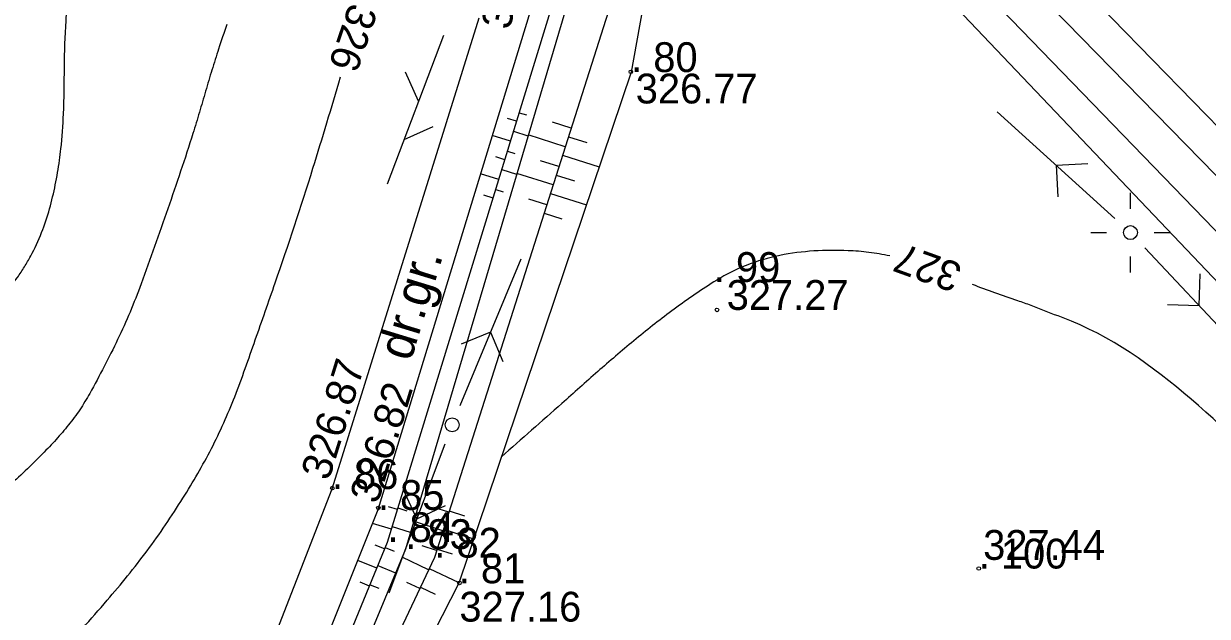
# Model space of a CAD drawing. Extents: x 4632591 to 4653165, y 5351032 to 5369868.
# Drawn here: x 4644706.6 to 4644766.2, y 5358525 to 5358554.8 of the extents above; entities that cross this region are included whole.
import ezdxf

# ---------------------------------------------------------------- set-up
doc = ezdxf.new("R2010")
doc.units = 0
for name, color, linetype in [('EUZPU_424', 7, 'Continuous'), ('SDRPK_420', 7, 'Continuous'), ('UEEPA_510', 7, 'Continuous'), ('UEETA_515', 7, 'Continuous'), ('UEETA_516', 7, 'Continuous'), ('UTTTA_521', 7, 'Continuous'), ('Warstwa 62', 7, 'Continuous'), ('WUKPS_403', 7, 'Continuous'), ('WUKPS_820', 7, 'Continuous'), ('WUKPS_823', 7, 'Continuous'), ('WUKPS_824', 7, 'Continuous'), ('WWRPH_811', 7, 'Continuous')]:
    doc.layers.add(name, color=color, linetype=linetype)

msp = doc.modelspace()

# ---------------------------------------------------------------- linework, layer by layer
at = {"layer": 'EUZPU_424'}
for points in [[(4644736.52, 5358573.425), (4644734.734, 5358569.58), (4644733.014, 5358558.487), (4644724.43, 5358530.37), (4644718.67, 5358515.99), (4644711.55, 5358501.11), (4644708.07, 5358496.17), (4644703.46, 5358490.97), (4644685.13, 5358478.64), (4644676.84, 5358472.22), (4644671.23, 5358466.74), (4644658.94, 5358454.03), (4644646.98, 5358446.31), (4644643, 5358444.41)], [(4644729.51, 5358555.12), (4644722.11, 5358531.42), (4644716.49, 5358516.97), (4644709.43, 5358502.48), (4644706.31, 5358497.61), (4644701.62, 5358493.26), (4644695.208, 5358490.354), (4644683.44, 5358482.53), (4644675.12, 5358474.36), (4644669.43, 5358468.46), (4644657.26, 5358456.17), (4644645.62, 5358448.34)]]:
    msp.add_lwpolyline(points, dxfattribs=at)
at = {"layer": 'SDRPK_420'}
msp.add_lwpolyline([(4644712.764, 5358603.261), (4644713.95, 5358602.19), (4644735.11, 5358581.89), (4644746.11, 5358570.7), (4644757.33, 5358559.27), (4644771.55, 5358544.69), (4644780.39, 5358535.5), (4644785.103, 5358530.718)], dxfattribs=at)
at = {"layer": 'UEEPA_510'}
for centre in [(4644762.316, 5358544.323), (4644728.165, 5358534.653)]:
    msp.add_circle(centre, 0.35, dxfattribs=at)
at = {"layer": 'UEETA_515'}
for p, q in [((4644762.316, 5358545.523), (4644762.316, 5358546.323)), ((4644760.316, 5358544.323), (4644761.116, 5358544.323)), ((4644763.516, 5358544.323), (4644764.316, 5358544.323)), ((4644762.316, 5358542.323), (4644762.316, 5358543.123))]:
    msp.add_line(p, q, dxfattribs=at)
at = {"layer": 'UEETA_516'}
for p, q in [((4644761.539, 5358545.029), (4644755.614, 5358550.404)), ((4644758.576, 5358547.716), (4644760.174, 5358547.794)), ((4644758.576, 5358547.716), (4644758.654, 5358546.119)), ((4644728.567, 5358535.623), (4644731.635, 5358543.011)), ((4644763.036, 5358543.559), (4644768.518, 5358537.732)), ((4644765.777, 5358540.645), (4644765.826, 5358542.244)), ((4644765.777, 5358540.645), (4644764.178, 5358540.694)), ((4644730.101, 5358539.317), (4644728.623, 5358538.706)), ((4644730.101, 5358539.317), (4644730.712, 5358537.839)), ((4644727.794, 5358533.67), (4644724.97, 5358526.186)), ((4644726.382, 5358529.928), (4644725.723, 5358531.386)), ((4644726.382, 5358529.928), (4644727.839, 5358530.587))]:
    msp.add_line(p, q, dxfattribs=at)
at = {"layer": 'UTTTA_521'}
for p, q in [((4644727.725, 5358554.238), (4644724.899, 5358546.754)), ((4644726.478, 5358550.935), (4644725.819, 5358552.392)), ((4644725.747, 5358548.999), (4644727.204, 5358549.658))]:
    msp.add_line(p, q, dxfattribs=at)
at = {"layer": 'WUKPS_403'}
for centre in [(4644737.163, 5358552.412), (4644741.498, 5358540.434), (4644722.135, 5358531.466), (4644724.452, 5358530.466), (4644754.68, 5358527.42), (4644754.68, 5358527.42), (4644728.532, 5358526.697)]:
    msp.add_circle(centre, 0.09, dxfattribs=at)
at = {"layer": 'WUKPS_820'}
for p, q in [((4644731.544, 5358550.352), (4644731.902, 5358550.242)), ((4644731.412, 5358549.923), (4644730.95, 5358550.065)), ((4644734.158, 5358549.572), (4644733.216, 5358549.873)), ((4644731.104, 5358548.921), (4644730.182, 5358549.205)), ((4644731.258, 5358549.422), (4644731.983, 5358549.199)), ((4644733.863, 5358548.646), (4644731.996, 5358549.241)), ((4644734.022, 5358549.145), (4644734.952, 5358548.848)), ((4644730.951, 5358548.421), (4644731.318, 5358548.308)), ((4644730.819, 5358547.991), (4644730.358, 5358548.133)), ((4644733.545, 5358547.647), (4644732.621, 5358547.942)), ((4644733.726, 5358548.218), (4644735.571, 5358547.63)), ((4644730.511, 5358546.99), (4644729.591, 5358547.272)), ((4644730.665, 5358547.491), (4644731.408, 5358547.262)), ((4644733.249, 5358546.721), (4644731.421, 5358547.304)), ((4644733.408, 5358547.22), (4644734.322, 5358546.928)), ((4644730.226, 5358546.06), (4644729.766, 5358546.201)), ((4644730.358, 5358546.489), (4644730.734, 5358546.374)), ((4644732.931, 5358545.722), (4644732.027, 5358546.011)), ((4644733.113, 5358546.293), (4644734.925, 5358545.715)), ((4644732.794, 5358545.295), (4644733.692, 5358545.008)), ((4644725.415, 5358530.395), (4644724.968, 5358530.532)), ((4644727.998, 5358530.251), (4644727.247, 5358530.491)), ((4644725.437, 5358530.467), (4644725.887, 5358530.329)), ((4644728.02, 5358530.323), (4644728.79, 5358530.077)), ((4644725.108, 5358529.394), (4644724.158, 5358529.685)), ((4644725.152, 5358529.537), (4644726.059, 5358529.258)), ((4644727.702, 5358529.325), (4644726.22, 5358529.797)), ((4644727.725, 5358529.396), (4644729.249, 5358528.91)), ((4644724.768, 5358528.405), (4644724.286, 5358528.603)), ((4644724.796, 5358528.474), (4644725.242, 5358528.29)), ((4644727.384, 5358528.327), (4644726.652, 5358528.56)), ((4644727.406, 5358528.398), (4644728.16, 5358528.158)), ((4644724.371, 5358527.437), (4644723.414, 5358527.83)), ((4644724.427, 5358527.575), (4644725.315, 5358527.211)), ((4644726.983, 5358527.362), (4644725.642, 5358527.996)), ((4644727.014, 5358527.429), (4644728.51, 5358526.722)), ((4644724.001, 5358526.539), (4644723.527, 5358526.734)), ((4644724.03, 5358526.608), (4644724.471, 5358526.427)), ((4644726.535, 5358526.416), (4644725.887, 5358526.722)), ((4644726.567, 5358526.483), (4644727.306, 5358526.134))]:
    msp.add_line(p, q, dxfattribs=at)
at = {"layer": 'WUKPS_823'}
for points in [[(4644783.887, 5358529.568), (4644744.81, 5358569.5), (4644739.48, 5358575.37)], [(4644738.78, 5358571.28), (4644736.75, 5358557.7), (4644727.27, 5358527.97), (4644721.2, 5358515.13)], [(4644780.988, 5358526.828), (4644742.7, 5358567.06), (4644738.78, 5358571.28)], [(4644719.6, 5358515.83), (4644724.91, 5358528.75), (4644733.96, 5358558.22)]]:
    msp.add_lwpolyline(points, dxfattribs=at)
at = {"layer": 'WUKPS_824'}
for points in [[(4644738.44, 5358574.02), (4644736.549, 5358569.507), (4644735.543, 5358564.04), (4644734.74, 5358558.49), (4644725.81, 5358528.4), (4644720.44, 5358515.5)], [(4644782.376, 5358528.141), (4644743.56, 5358568.22), (4644738.44, 5358574.02)], [(4644739.72, 5358566.1), (4644738.06, 5358557.26), (4644737.18, 5358552.4), (4644728.5, 5358526.68), (4644722.2, 5358514.32)]]:
    msp.add_lwpolyline(points, dxfattribs=at)
at = {"layer": 'WWRPH_811'}
for points in [[(4644694.944, 5358538.645), (4644699.243, 5358539.259), (4644701.331, 5358539.575), (4644702.373, 5358539.754), (4644702.894, 5358539.852), (4644703.414, 5358539.955), (4644703.982, 5358540.124), (4644704.513, 5358540.38), (4644705.468, 5358541.113), (4644706.279, 5358542.065), (4644706.631, 5358542.595), (4644706.948, 5358543.146), (4644707.496, 5358544.326), (4644707.896, 5358545.518), (4644708.185, 5358546.728), (4644708.397, 5358547.96), (4644708.472, 5358548.541), (4644708.598, 5358550.295), (4644708.645, 5358552.642), (4644708.729, 5358554.984), (4644708.844, 5358556.146), (4644709.039, 5358557.299), (4644709.543, 5358559.426)], [(4644716.821, 5358554.799), (4644716.406, 5358553.56), (4644716.071, 5358552.503), (4644715.754, 5358551.441), (4644715.44, 5358550.377), (4644715.115, 5358549.317), (4644713.847, 5358545.516), (4644713.182, 5358543.625), (4644712.504, 5358541.737), (4644711.948, 5358540.325), (4644711.324, 5358538.944), (4644710.644, 5358537.584), (4644709.921, 5358536.235), (4644709.417, 5358535.411), (4644708.849, 5358534.642), (4644708.223, 5358533.909), (4644707.544, 5358533.195), (4644706.673, 5358532.332), (4644705.756, 5358531.536), (4644704.765, 5358530.898), (4644703.671, 5358530.51), (4644697.089, 5358529.19)], [(4644699.856, 5358516.59), (4644705.496, 5358520.583), (4644706.947, 5358521.741), (4644708.288, 5358523.031), (4644709.556, 5358524.406), (4644710.793, 5358525.821), (4644711.826, 5358527.052), (4644712.807, 5358528.313), (4644713.735, 5358529.614), (4644714.61, 5358530.962), (4644716.045, 5358533.457), (4644717.217, 5358536.067), (4644718.253, 5358538.926), (4644719.257, 5358541.792), (4644721.157, 5358547.558), (4644722.55, 5358552.153)], [(4644750.196, 5358543.15), (4644749.673, 5358543.253), (4644749.148, 5358543.329), (4644748.623, 5358543.381), (4644748.1, 5358543.412), (4644746.382, 5358543.397), (4644744.663, 5358543.171), (4644742.973, 5358542.673), (4644742.148, 5358542.302), (4644741.741, 5358542.083), (4644741.34, 5358541.84), (4644739.223, 5358540.38), (4644737.308, 5358538.877), (4644735.496, 5358537.329), (4644733.691, 5358535.732), (4644730.645, 5358533.037)], [(4644779.107, 5358525.051), (4644771.581, 5358530.337), (4644759.346, 5358539.864), (4644757.992, 5358540.387), (4644757.317, 5358540.652), (4644756.641, 5358540.892), (4644755.498, 5358541.288), (4644754.371, 5358541.708)]]:
    msp.add_spline(points, degree=3, dxfattribs=at)

# ---------------------------------------------------------------- texts
at = {"layer": 'EUZPU_424'}
msp.add_text('dr.gr.', height=1.8, rotation=73.0223, dxfattribs=at).set_placement((4644726.078, 5358537.797))
at = {"layer": 'Warstwa 62'}
for s, p in [('. 80', (4644737.18, 5358552.4)), ('. 99', (4644741.34, 5358541.84)), ('. 86', (4644722.11, 5358531.42)), ('. 85', (4644724.43, 5358530.37)), ('. 84', (4644724.91, 5358528.75)), ('. 83', (4644725.81, 5358528.4)), ('. 82', (4644727.27, 5358527.97)), ('. 100', (4644754.68, 5358527.42)), ('. 81', (4644728.5, 5358526.68))]:
    msp.add_text(s, height=1.5, dxfattribs=at).set_placement(p)
at = {"layer": 'WUKPS_403'}
for s, rotation, p in [('326.54', 79.01987, (4644731.093, 5358554.494)), ('326.87', 72.65974, (4644721.955, 5358531.796)), ('326.82', 73.0223, (4644724.418, 5358530.626))]:
    msp.add_text(s, height=1.5, rotation=rotation, dxfattribs=at).set_placement(p)
for s, p in [('326.77', (4644737.41, 5358550.821)), ('327.27', (4644741.989, 5358540.434)), ('327.44', (4644754.902, 5358527.857)), ('327.16', (4644728.532, 5358524.751))]:
    msp.add_text(s, height=1.5, dxfattribs=at).set_placement(p)
at = {"layer": 'WWRPH_811'}
for s, rotation, p in [('326', 251.14812, (4644723.017, 5358555.94)), ('327', 160.14604, (4644753.931, 5358542.695))]:
    msp.add_text(s, height=1.5, rotation=rotation, dxfattribs=at).set_placement(p)

doc.saveas('drawing.dxf')
